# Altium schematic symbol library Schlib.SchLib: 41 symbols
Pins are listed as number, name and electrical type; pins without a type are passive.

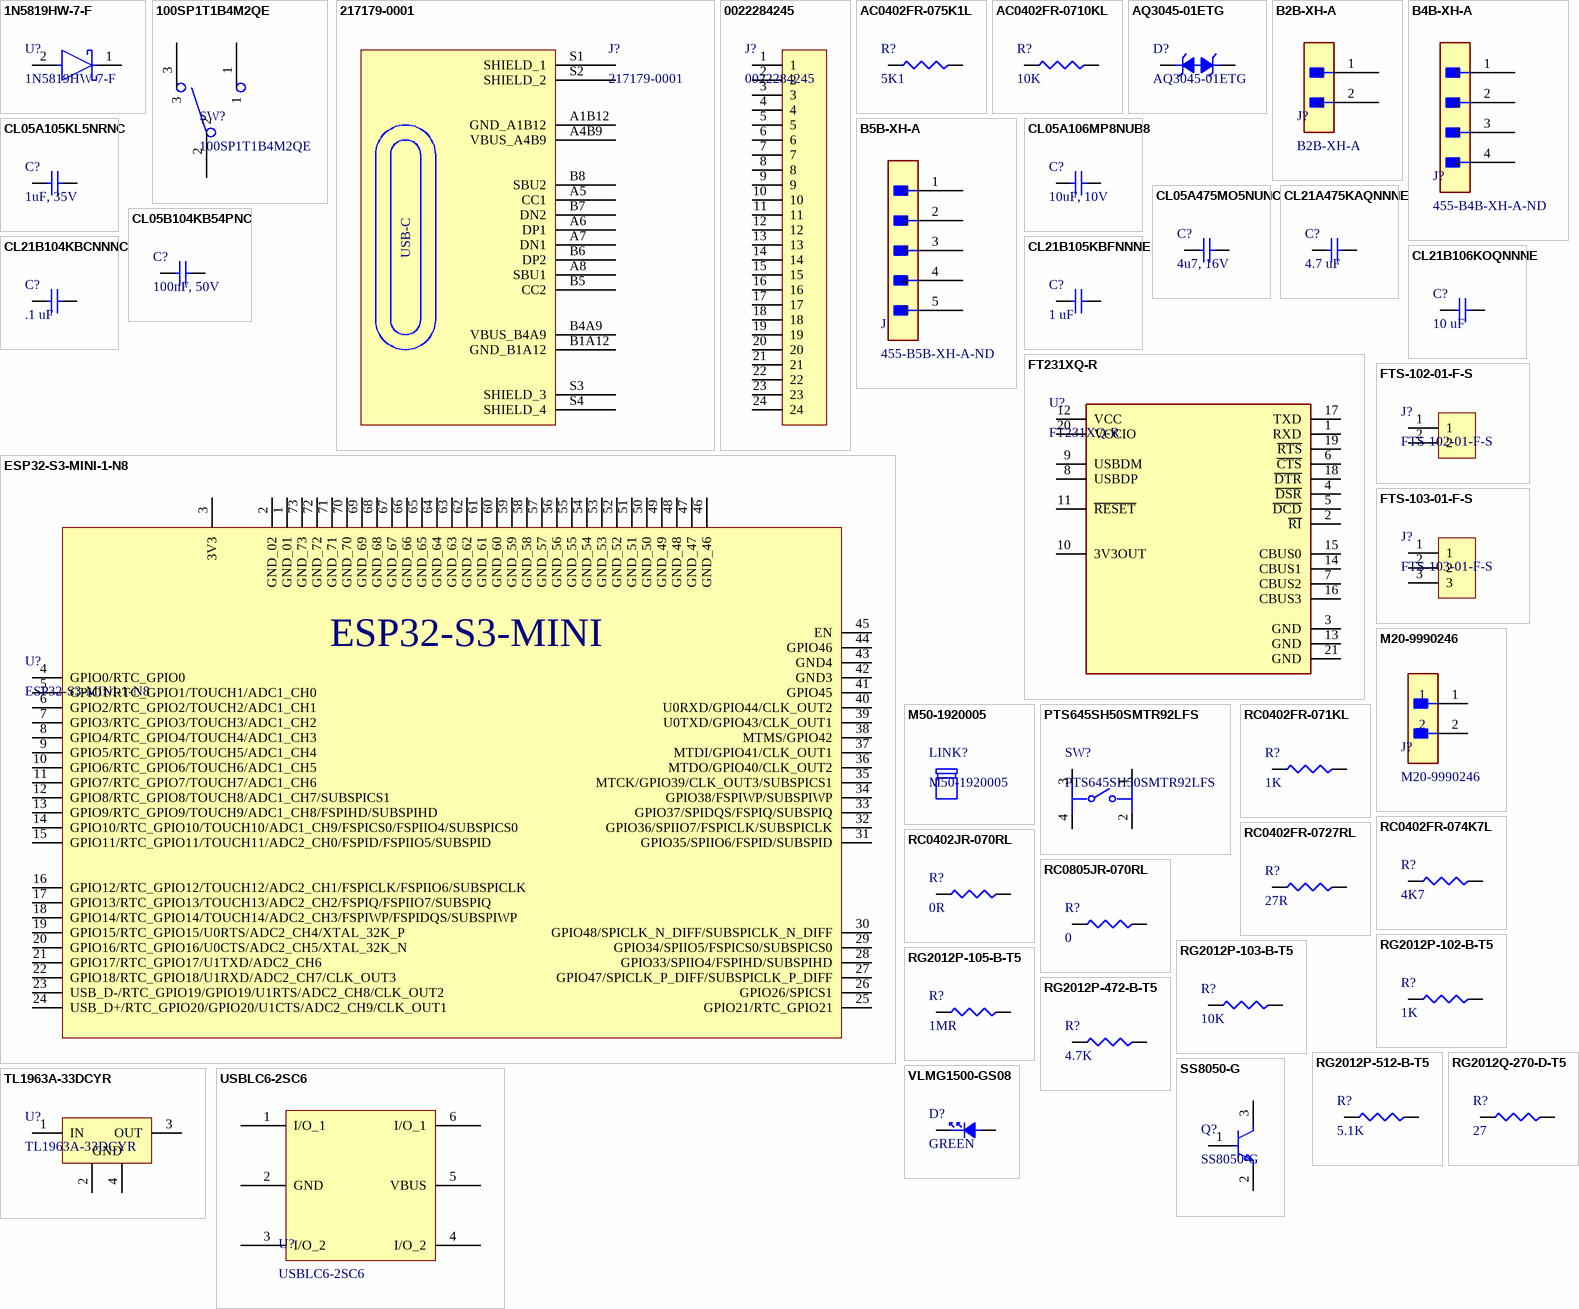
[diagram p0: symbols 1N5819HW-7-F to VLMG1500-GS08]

## 1N5819HW-7-F
designator U?
DIODE SCHOTTKY 40V 1A SOD123; Manufacturer: Diodes Inc.; Value: 50pF; Element Configuration: Single; Forward Voltage: 750mV; Max Forward Surge Current (Ifsm): 25A; Max Junction Temperature (Tj): 125°C; Max Power Dissipation: 450mW; Number of Elements: 1; Peak Reverse Current: 1mA; Polarity: Standard
footprint FP-SOD123-IPC_B
pins: 1 C, 2 A

## 100SP1T1B4M2QE
designator SW?
Switch Toggle ON None ON SPDT Round Lever PC Pins 5A 250VAC 28VDC PC Mount; Manufacturer: E-Switch; Actuator Length: 10.414mm; Actuator Material: Brass, Chrome; Contact Voltage Rating (AC): 120V; Electrical Life: 50kcycles; Illumination Type: Illuminated, Non-Illuminated; Max Voltage Rating (DC): 28V; Number of Positions: 2; Sealable: EPOXY TERMINAL SEALED; Switch Function: On-On
footprint 100SP1T1_EWI
pins: 1, 2, 3

## 217179-0001
designator J?
CONN RCP USB2.0 TYP C 24P SMD RA; Manufacturer: Molex
footprint FP-2171790001-MFG
pins: A1B12 GND_A1B12, A4B9 VBUS_A4B9, A5 CC1, A6 DP1, A7 DN1, A8 SBU1, B1A12 GND_B1A12, B4A9 VBUS_B4A9, B5 CC2, B6 DP2, B7 DN2, B8 SBU2, S1 SHIELD_1, S2 SHIELD_2, S3 SHIELD_3, S4 SHIELD_4

## 0022284245
designator J?
CONN HEADER VERT 24POS 2.54MM; Manufacturer: Molex; Connector Type: BOARD CONNECTOR; Option: General Purpose; Filter Feature: No; Mating Information: MULTIPLE MATING PARTS AVAILABLE; Number of Rows Loaded: 1; Number of Contacts: 24
footprint HDR_1X24_2.54MM
pins: 1, 2, 3, 4, 5, 6, 7, 8, 9, 10, 11, 12, 13, 14, 15, 16, 17, 18, 19, 20, 21, 22, 23, 24

## AC0402FR-075K1L
designator R?, comment 5K1
RES SMD 5.1K OHM 1% 1/16W 0402; Manufacturer: Yageo; Manufacturer Part Number: AC0402FR-075K1L; Additional Feature: LASER TRIMMABLE; Power: 62.5mW; Rated Temperature: 70°C; Value: 5.1kR; Temperature Coefficient: 100ppm/°C; Working Voltage: 50V; Package Height: 0.32mm; Package Length: 1mm; Package Width: 0.5mm; Reference Standard: AEC-Q200
footprint RESC1005X37N
pins: 1, 2

## AC0402FR-0710KL
designator R?, comment 10K
RES SMD 10K OHM 1% 1/16W 0402; Manufacturer: Yageo; Manufacturer Part Number: AC0402FR-0710KL; Additional Feature: LASER TRIMMABLE; Power: 62.5mW; Rated Temperature: 70°C; Value: 10kR; Temperature Coefficient: 100ppm/°C; Working Voltage: 50V; Package Height: 0.32mm; Package Length: 1mm; Package Width: 0.5mm; Reference Standard: AEC-Q200
footprint RESC1005X37N
pins: 1, 2

## AQ3045-01ETG
designator D?
TVS DIODE 5.3VWM 12VC SOD882; Manufacturer: Littelfuse; Diode Element Material: SILICON; Package Body Material: Plastic; Polarity: Bidirectional; Max Breakdown Voltage: 9V; Min Breakdown Voltage: 6.8V; Diode Type: TRANS VOLTAGE SUPPRESSOR; Non-rep Peak Rev Power Dis-Max: 40W; Number of Elements: 1; Rep Pk Reverse Voltage-Max: 5.3V; Reference Standard: AEC-Q101
footprint SOD882
pins: 1, 2

## B2B-XH-A
designator J?
Board Connector, 2 Contact(s), 1 Row(s), Male, Straight, Solder Terminal; Manufacturer: JST; Contact Resistance: 20mΩ; Current Rating: 3A; Insulation Resistance: 1GΩ
footprint CONN_B2B-XH-A_JST
pins: 1, 2

## B4B-XH-A
designator J?, comment 455-B4B-XH-A-ND
Board Connector, 4 Contact(s), 1 Row(s), Male, Straight, Solder Terminal; Manufacturer: JST; Contact Resistance: 20mΩ; Current Rating: 3A; Insulation Resistance: 1GΩ
footprint CONN_B4B-XH-A_JST
pins: 1, 2, 3, 4

## B5B-XH-A
designator J, comment 455-B5B-XH-A-ND
Board Connector, 5 Contact(s), 1 Row(s), Male, Straight, 0.098 inch Pitch, Solder Terminal; Manufacturer: JST; Contact Resistance: 20mΩ; Current Rating: 3A; Insulation Resistance: 1GΩ
footprint CONN_B5B-XH-A_JST
pins: 1, 2, 3, 4, 5

## CL05A105KL5NRNC
designator C?, comment 1uF, 35V
CAP CER 1UF 35V X5R 0402; Manufacturer: Samsung; Manufacturer Part Number: CL05A105KL5NRNC; Dielectric Material: Ceramic; Multilayer: Yes; Tolerance  (fill in as +-): 10%
footprint CAPC1005X55N
pins: 1, 2

## CL05A106MP8NUB8
designator C?, comment 10uF, 10V
CAP CER 10UF 10V X5R 0402; Manufacturer: Samsung; Manufacturer Part Number: CL05A106MP8NUB8; Dielectric Material: Ceramic; Multilayer: Yes; Tolerance  (fill in as +-): 20%
footprint CAPC1005X55N
pins: 1, 2

## CL05A475MO5NUNC
designator C?, comment 4u7, 16V
CAP CER 4.7UF 16V X5R 0402; Manufacturer: Samsung; Manufacturer Part Number: CL05A475MO5NUNC; Dielectric Material: Ceramic; Multilayer: Yes; Tolerance  (fill in as +-): 20%
footprint CAPC1005X55N
pins: 1, 2

## CL05B104KB54PNC
designator C?, comment 100nF, 50V
CAP CER 0.1UF 50V X7R 0402; Manufacturer: Samsung; Manufacturer Part Number: CL05B104KB54PNC; Dielectric Material: Ceramic
footprint CAPC1005X55N
pins: 1, 2

## CL21A475KAQNNNE
designator C?, comment 4.7 uF
25V 4.7uF X5R ±10% 0805 Multilayer Ceramic Capacitors MLCC - SMD/SMT ROHS; Manufacturer: Samsung Electro-Mechanics; Manufacturer Part Number: CL21A475KAQNNNE; Value: 4.7µF
footprint CAP_CL21_SAM-L
pins: 1, 2

## CL21B104KBCNNNC
designator C?, comment .1 uF
50V 100nF X7R ±10% 0805 Multilayer Ceramic Capacitors MLCC - SMD/SMT ROHS; Manufacturer: Samsung Electro-Mechanics; Manufacturer Part Number: CL21B104KBCNNNC
footprint CAP_CL21_SAM-L
pins: 1, 2

## CL21B105KBFNNNE
designator C?, comment 1 uF
50V 1uF X7R ±10% 0805 Multilayer Ceramic Capacitors MLCC - SMD/SMT ROHS; Manufacturer: Samsung Electro-Mechanics; Manufacturer Part Number: CL21B105KBFNNNE; Value: 1µF
footprint CAP_CL21_SAM-L
pins: 1, 2

## CL21B106KOQNNNE
designator C?, comment 10 uF
16V 10uF X7R ±10% 0805 Multilayer Ceramic Capacitors MLCC - SMD/SMT ROHS; Manufacturer: Samsung Electro-Mechanics; Manufacturer Part Number: CL21B106KOQNNNE; Value: 10µF
footprint CAP_CL21_SAM-L
pins: 1, 2

## ESP32-S3-MINI-1-N8
designator U?
SMD Module, ESP32-S3FN8, 8 mb Sp; Manufacturer: Espressif Systems
footprint XCVR_ESP32-S3-MINI-1-N8
pins: 1 GND_01, 2 GND_02, 3 3V3, 4 GPIO0/RTC_GPIO0, 5 GPIO1/RTC_GPIO1/TOUCH1/ADC1_CH0, 6 GPIO2/RTC_GPIO2/TOUCH2/ADC1_CH1, 7 GPIO3/RTC_GPIO3/TOUCH3/ADC1_CH2, 8 GPIO4/RTC_GPIO4/TOUCH4/ADC1_CH3, 9 GPIO5/RTC_GPIO5/TOUCH5/ADC1_CH4, 10 GPIO6/RTC_GPIO6/TOUCH6/ADC1_CH5, 11 GPIO7/RTC_GPIO7/TOUCH7/ADC1_CH6, 12 GPIO8/RTC_GPIO8/TOUCH8/ADC1_CH7/SUBSPICS1, 13 GPIO9/RTC_GPIO9/TOUCH9/ADC1_CH8/FSPIHD/SUBSPIHD, 14 GPIO10/RTC_GPIO10/TOUCH10/ADC1_CH9/FSPICS0/FSPIIO4/SUBSPICS0, 15 GPIO11/RTC_GPIO11/TOUCH11/ADC2_CH0/FSPID/FSPIIO5/SUBSPID, 16 GPIO12/RTC_GPIO12/TOUCH12/ADC2_CH1/FSPICLK/FSPIIO6/SUBSPICLK, 17 GPIO13/RTC_GPIO13/TOUCH13/ADC2_CH2/FSPIQ/FSPIIO7/SUBSPIQ, 18 GPIO14/RTC_GPIO14/TOUCH14/ADC2_CH3/FSPIWP/FSPIDQS/SUBSPIWP, 19 GPIO15/RTC_GPIO15/U0RTS/ADC2_CH4/XTAL_32K_P, 20 GPIO16/RTC_GPIO16/U0CTS/ADC2_CH5/XTAL_32K_N, 21 GPIO17/RTC_GPIO17/U1TXD/ADC2_CH6, 22 GPIO18/RTC_GPIO18/U1RXD/ADC2_CH7/CLK_OUT3, 23 USB_D-/RTC_GPIO19/GPIO19/U1RTS/ADC2_CH8/CLK_OUT2, 24 USB_D+/RTC_GPIO20/GPIO20/U1CTS/ADC2_CH9/CLK_OUT1, 25 GPIO21/RTC_GPIO21, 26 GPIO26/SPICS1, 27 GPIO47/SPICLK_P_DIFF/SUBSPICLK_P_DIFF, 28 GPIO33/SPIIO4/FSPIHD/SUBSPIHD, 29 GPIO34/SPIIO5/FSPICS0/SUBSPICS0, 30 GPIO48/SPICLK_N_DIFF/SUBSPICLK_N_DIFF, 31 GPIO35/SPIIO6/FSPID/SUBSPID, 32 GPIO36/SPIIO7/FSPICLK/SUBSPICLK, 33 GPIO37/SPIDQS/FSPIQ/SUBSPIQ, 34 GPIO38/FSPIWP/SUBSPIWP, 35 MTCK/GPIO39/CLK_OUT3/SUBSPICS1, 36 MTDO/GPIO40/CLK_OUT2, 37 MTDI/GPIO41/CLK_OUT1, 38 MTMS/GPIO42, 39 U0TXD/GPIO43/CLK_OUT1, 40 U0RXD/GPIO44/CLK_OUT2, 41 GPIO45, 42 GND3, 43 GND4, 44 GPIO46, 45 EN, 46 GND_46, 47 GND_47, 48 GND_48, 49 GND_49, 50 GND_50, 51 GND_51, 52 GND_52, 53 GND_53, 54 GND_54, 55 GND_55, 56 GND_56, 57 GND_57, 58 GND_58, 59 GND_59, 60 GND_60, 61 GND_61, 62 GND_62, 63 GND_63, 64 GND_64, 65 GND_65, 66 GND_66, 67 GND_67, 68 GND_68, 69 GND_69, 70 GND_70, 71 GND_71, 72 GND_72, 73 GND_73

## FT231XQ-R
designator U?
IC USB SERIAL FULL UART 20QFN; Manufacturer: FTDI; Power Supplies: 3.3/5V; Max Supply Current: 8.4mA; Max Supply Voltage: 5.5V; Min Supply Voltage: 2.97V; Nominal Supply Voltage: 5V; Qualification Status: Not Qualified
footprint FP-QFN-20-IPC_B
pins: 1 RXD, 2 ~{RI}, 3 GND, 4 ~{DSR}, 5 ~{DCD}, 6 ~{CTS}, 7 CBUS2, 8 USBDP, 9 USBDM, 10 3V3OUT, 11 ~{RESET}, 12 VCC, 13 GND, 14 CBUS1, 15 CBUS0, 16 CBUS3, 17 TXD, 18 ~{DTR}, 19 ~{RTS}, 20 VCCIO, 21 GND

## FTS-102-01-F-S
designator J?
CONN HEADER VERT 2POS 1.27MM; Manufacturer: Samtec; Manufacturer Series: FTS; Connector Type: BOARD CONNECTOR; Option: General Purpose; Additional Feature: Low Profile; Filter Feature: No; Number of Rows Loaded: 1; Number of Contacts: 2
footprint HDR_1X2_1.27MM
pins: 1, 2

## FTS-103-01-F-S
designator J?
CONN HEADER VERT 3POS 1.27MM; Manufacturer: Samtec; Manufacturer Series: FTS; Connector Type: BOARD CONNECTOR; Option: General Purpose; Additional Feature: Low Profile; Filter Feature: No; Number of Rows Loaded: 1; Number of Contacts: 3
footprint HDR_1X3_1.27MM
pins: 1, 2, 3

## M20-9990246
designator J?
Connector Header Through Hole 2 position 0.100" (2.54mm); Manufacturer: Harwin; Connector Type: Male Pin; Contact Resistance: 30mΩ; Current Rating: 3A; Dielectric Material: Polyamide; Gender: Male; Insulation Resistance: 1GΩ; Number of Contacts: 2; Voltage Rating (AC): 750V
footprint CONN2_M20-999_1x2_HRW
pins: 1, 2

## M50-1920005
designator LINK?  (mechanical)
CONN SHUNT 1.27MM RED; Manufacturer: Harwin; Manufacturer Series: M50; Connector Type: Interconnection Device; Body/Shell Style: PLUG; Contact Pattern: RECTANGULAR; Contact Resistance: 20mR; Durability: 300Cycles; Insulation Resistance: 1GR; Number Of Connectors: 1; Rated Current (Signal): 1A; Number of Contacts: 2; Dielectric Withstanding Voltage (AC): 500V; Body Breadth: 0.059inch; Body Length: 0.098inch; Mating Contact Pitch: 0.05inch; Body Depth: 0.118inch; Reference Standard: UL; Reliability: COMMERCIAL

## PTS645SH50SMTR92LFS
designator SW?
SWITCH TACTILE SPST-NO 0.05A 12V; Manufacturer: ITT C&K; Manufacturer Series: PTS645; Actuator Type: Pushbutton; Contact Current(DC)-Max: 50mA; Contact DC Max Rating R Load: 0.05A@12VDC; Contact Resistance: 0.1mR; Dielectric Withstand Volts: 250VACV; Electrical Life: 100000Cycles; Insulation Resistance: 100GR; PCB Hole Count: 4; Switch Action: MOMENTARY; Switch Function: SPST; Switch Type: Keypad; Body Breadth: 5.9944inch; Body Height: 3.4544mm; Body Length or Diameter: 5.9944mm
footprint FP-PTS645SH50SMTR92LFS-MFG
pins: 1, 2, 3, 4

## RC0402FR-071KL
designator R?, comment 1K
RES 1K OHM 1% 1/16W 0402; Manufacturer: Yageo; Manufacturer Part Number: RC0402FR-071KL; Additional Feature: LASER TRIMMABLE; Power: 62.5mW; Rated Temperature: 70°C; Value: 1kR; Temperature Coefficient: 100ppm/°C; Working Voltage: 50V; Package Height: 0.35mm; Package Length: 1mm; Package Width: 0.5mm
footprint RESC1005X37N
pins: 1, 2

## RC0402FR-074K7L
designator R?, comment 4K7
RES 4.7K OHM 1% 1/16W 0402; Manufacturer: Yageo; Manufacturer Part Number: RC0402FR-074K7L; Additional Feature: LASER TRIMMABLE; Power: 62.5mW; Rated Temperature: 70°C; Value: 4.7kR; Temperature Coefficient: 100ppm/°C; Working Voltage: 50V; Package Height: 0.35mm; Package Length: 1mm; Package Width: 0.5mm
footprint RESC1005X37N
pins: 1, 2

## RC0402FR-0727RL
designator R?, comment 27R
RES 27 OHM 1% 1/16W 0402; Manufacturer: Yageo; Manufacturer Part Number: RC0402FR-0727RL; Additional Feature: LASER TRIMMABLE; Power: 62.5mW; Rated Temperature: 70°C; Temperature Coefficient: 100ppm/°C; Working Voltage: 50V; Package Height: 0.35mm; Package Length: 1mm; Package Width: 0.5mm
footprint RESC1005X37N
pins: 1, 2

## RC0402JR-070RL
designator R?, comment 0R
RES 0 OHM JUMPER 1/16W 0402; Manufacturer: Yageo; Manufacturer Part Number: RC0402JR-070RL; Power: 62.5mW; Rated Temperature: 70°C; Package Height: 0.35mm; Package Length: 1mm; Package Width: 0.5mm
footprint RESC1005X37N
pins: 1, 2

## RC0805JR-070RL
designator R?, comment 0
GENERAL PURPOSE CHIP RESISTOR Metal Glaze/thick Film, 0.125W, 0ohm, Surface Mount, 0805; Manufacturer: Yageo Group; Manufacturer Part Number: RC0805JR-070RL; Power Dissipation: 125mW; Value: 0Ω; Temperature Coefficient: 300ppm/°C; Tolerance: 5%; Voltage Rating: 150V
footprint RES_1220_SUS-L
pins: 1, 2

## RG2012P-102-B-T5
designator R?, comment 1K
Res Thin Film 0805 1K Ohm 0.1% 0.125W(1/8W) ±25ppm/C Sulfur Resistant Pad SMD Automotive T/R; Manufacturer: Susumu; Manufacturer Part Number: RG2012P-102-B-T5; Max Power Dissipation: 125mW; Value: 1kΩ; Temperature Coefficient: 25ppm/°C; Voltage Rating: 150V
footprint RES_1220_SUS-L
pins: 1, 2

## RG2012P-103-B-T5
designator R?, comment 10K
Res Thin Film 0805 10K Ohm 0.1% 0.125W(1/8W) ±25ppm/C Sulfur Resistant Pad SMD Automotive T/R; Manufacturer: Susumu; Manufacturer Part Number: RG2012P-103-B-T5; Power Dissipation: 125mW; Value: 10kΩ; Temperature Coefficient: 25ppm/°C; Voltage Rating: 150V
footprint RES_1220_SUS-L
pins: 1, 2

## RG2012P-105-B-T5
designator R?, comment 1MR
Res Thin Film 0805 1M Ohm 0.1% 0.125W(1/8W) ±25ppm/C Sulfur Resistant Pad SMD Automotive T/R; Manufacturer: Susumu; Manufacturer Part Number: RG2012P-105-B-T5; Power Dissipation: 125mW; Value: 1MΩ; Temperature Coefficient: 25ppm/°C; Voltage Rating: 150V
footprint RES_1220_SUS-L
pins: 1, 2

## RG2012P-472-B-T5
designator R?, comment 4.7K
Res Thin Film 0805 4.7K Ohm 0.1% 0.125W(1/8W) ±25ppm/C Sulfur Resistant Pad SMD Automotive T/R; Manufacturer: Susumu; Manufacturer Part Number: RG2012P-472-B-T5; Power Dissipation: 125mW; Value: 4.7kΩ; Temperature Coefficient: 25ppm/°C; Voltage Rating: 150V
footprint RES_1220_SUS-L
pins: 1, 2

## RG2012P-512-B-T5
designator R?, comment 5.1K
Res Thin Film 0805 5.1K Ohm 0.1% 0.125W(1/8W) ±25ppm/C Sulfur Resistant Pad SMD Automotive T/R; Manufacturer: Susumu; Manufacturer Part Number: RG2012P-512-B-T5; Max Power Dissipation: 125mW; Value: 5.1kΩ; Temperature Coefficient: 25ppm/°C; Voltage Rating: 150V
footprint RES_1220_SUS-L
pins: 1, 2

## RG2012Q-270-D-T5
designator R?, comment 27
Fixed Resistor, Thin Film, 0.125W, 27ohm, 150V, 0.5% +/-Tol, 50ppm/Cel, Surface Mount, 0805; Manufacturer: Susumu; Manufacturer Part Number: RG2012Q-270-D-T5; Power Dissipation: 125mW; Value: 27Ω; Temperature Coefficient: 50ppm/°C
footprint RES_1220_SUS-L
pins: 1, 2

## SS8050-G
designator Q?
TRANS NPN 25V 1.5A SOT23-3; Manufacturer: Comchip
footprint FP-SS8050-G-IPC_B
pins: 1 B, 2 E, 3 C

## TL1963A-33DCYR
designator U?
IC REG LINEAR 3.3V 1.5A SOT223-4; Manufacturer: Texas Instruments; Package Body Material: Plastic; Adjustability: FIXED; Dropout Voltage1-Max: 550mV; Dropout Voltage1-Nom: 340mV; Input Voltage Absolute-Max: 20V; Min Input Voltage: 3.8V; Line Regulation-Max: 0.01%; Load Regulation-Max: 0.07%; Channels: 1; Output Voltage1-Max: 3.4V; Output Voltage1-Min: 3.2V; Regulator Type: FIXED POSITIVE SINGLE OUTPUT LDO REGULATOR; Voltage Tolerance-Max: 3%; Qualification Status: Not Qualified
footprint DCY0004A_N (SOT223, 4-Leads, Body 6.7x3.7mm, Pitch 2.3mm, IPC Medium Density)
pins: 1 IN (power) "Input. Power is supplied to the device through the IN pin. A bypass capacitor is required on this pin if the device is more than six inches away from the main input filter capacitor. In general, the output impedance of a (See Datasheet)", 2 GND (power) "Ground", 3 OUT (power) "Output. The output supplies power to the load. A minimum output capacitor (ceramic) of 10 uF is required to prevent oscillations. Larger output capacitors are required for applications with large transient loads to limit (See Datasheet)", 4 GND (power) "Ground"

## USBLC6-2SC6
designator U?
17V Clamp 5A (8/20µs) Ipp Tvs Diode Surface Mount SOT-23-6; Manufacturer: STMicroelectronics; Breakdown Voltage: 6V; Value: 2.5pF; Data Rate: 480Mbps; Direction: Unidirectional; Element Configuration: Dual; ESD Protection: Yes; Forward Voltage: 1.1V; Leakage Current: 150nA; Max Junction Temperature (Tj): 125°C; Max Repetitive Reverse Voltage (Vrrm): 5.25V; Number of Bidirectional Channels: 2; Number of Elements: 1; Reverse Standoff Voltage: 5V; Test Current: 1mA
footprint SOT23-6L_STM
pins: 1 I/O_1, 2 GND, 3 I/O_2, 4 I/O_2, 5 VBUS, 6 I/O_1

## VLMG1500-GS08
designator D?, comment GREEN
LED YLW-GRN 0402 SMD; Manufacturer: Vishay; Manufacturer Part Number: VLMG1500-GS08; Color: Green,Yellow; Lens Color: Clear; Viewing Angle: 130°; Forward Current: 30mA; Forward Voltage: 2V; Luminous Intensity: 35mcd; Dominant Wavelength: 571nm; Test Current: 20mA; Number of Elements: 1; Power Dissipation: 75mW; Lens Style: Rectangular; Reverse Voltage: 5V
footprint LED0402G
pins: 1, 2

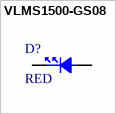
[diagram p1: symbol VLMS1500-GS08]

## VLMS1500-GS08
designator D?, comment RED
LED RED 0402 SMD; Manufacturer: Vishay; Manufacturer Part Number: VLMS1500-GS08; Shape: Rectangular; Forward Current: 30mA; Forward Voltage: 2.4V; Luminous Intensity-Nom: 54mcd; Channels: 1; Optoelectronic Device Type: SINGLE COLOR LED; Reverse Voltage-Max: 5V; Viewing Angle: 130°; Overall Height: 0.35mm
footprint LED0402R
pins: 1, 2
